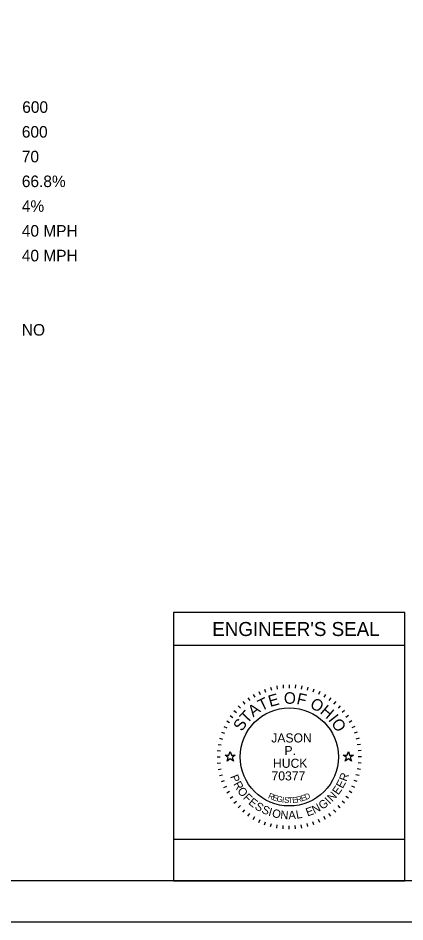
# Model space of a CAD drawing. Extents: x 0 to 34, y 0 to 22.
# Drawn here: x 7.69 to 12.37, y 0 to 10.95 of the extents above; entities that cross this region are included whole.
import ezdxf

# ---------------------------------------------------------------- set-up
doc = ezdxf.new("R2010")
doc.units = 0
for name, color, linetype in [('Default', 7, 'Continuous'), ('SH_Border', 7, 'Continuous'), ('SH_Cut_Line', 7, 'Continuous'), ('SH_Data', 7, 'Continuous'), ('SH_Text', 7, 'Continuous')]:
    doc.layers.add(name, color=color, linetype=linetype)

msp = doc.modelspace()

# ---------------------------------------------------------------- linework, layer by layer
at = {"layer": 'Default'}
for points in [[(10.198, 2.02), (10.245, 2.02), (10.26, 2.065), (10.274, 2.02), (10.321, 2.02), (10.283, 1.992), (10.298, 1.948), (10.26, 1.975), (10.222, 1.948), (10.236, 1.992)], [(11.628, 2.02), (11.675, 2.02), (11.69, 2.065), (11.704, 2.02), (11.751, 2.02), (11.713, 1.992), (11.728, 1.948), (11.69, 1.975), (11.652, 1.948), (11.666, 1.992)]]:
    msp.add_lwpolyline(points, close=True, dxfattribs=at)
at = {"layer": 'SH_Border'}
msp.add_lwpolyline([(1.5, 21.5), (33.5, 21.5), (33.5, 0.5), (1.5, 0.5)], close=True, dxfattribs=at)
at = {"layer": 'SH_Cut_Line'}
msp.add_lwpolyline([(0, 0), (34, 0), (34, 22), (0, 22)], close=True, dxfattribs=at)
at = {"layer": 'SH_Data'}
for p, q in [((12.375, 3.75), (9.575, 3.75)), ((9.575, 3.75), (9.575, 0.5)), ((12.375, 0.5), (12.375, 3.75)), ((12.375, 3.35), (9.575, 3.35)), ((10.823, 2.862), (10.83, 2.822)), ((10.899, 2.872), (10.902, 2.832)), ((10.975, 2.875), (10.975, 2.835)), ((11.051, 2.872), (11.048, 2.832)), ((11.127, 2.862), (11.12, 2.822)), ((10.537, 2.758), (10.557, 2.723)), ((10.605, 2.793), (10.622, 2.757)), ((10.676, 2.822), (10.689, 2.785)), ((10.748, 2.845), (10.759, 2.807)), ((11.201, 2.845), (11.191, 2.807)), ((11.274, 2.822), (11.26, 2.785)), ((11.345, 2.793), (11.328, 2.757)), ((11.412, 2.758), (11.392, 2.723)), ((10.412, 2.67), (10.438, 2.64)), ((10.473, 2.717), (10.496, 2.684)), ((11.477, 2.717), (11.454, 2.684)), ((11.537, 2.67), (11.512, 2.64)), ((10.304, 2.562), (10.335, 2.537)), ((10.356, 2.619), (10.384, 2.59)), ((11.593, 2.619), (11.565, 2.59)), ((11.645, 2.562), (11.614, 2.537)), ((10.217, 2.438), (10.252, 2.418)), ((10.258, 2.502), (10.291, 2.479)), ((11.692, 2.502), (11.659, 2.479)), ((11.733, 2.438), (11.698, 2.418)), ((10.182, 2.37), (10.218, 2.353)), ((11.768, 2.37), (11.732, 2.353)), ((10.13, 2.226), (10.168, 2.216)), ((10.153, 2.299), (10.19, 2.286)), ((11.797, 2.299), (11.759, 2.286)), ((11.82, 2.226), (11.781, 2.216)), ((10.113, 2.152), (10.152, 2.145)), ((11.836, 2.152), (11.797, 2.145)), ((10.1, 2), (10.14, 2)), ((10.103, 2.076), (10.143, 2.073)), ((11.846, 2.076), (11.807, 2.073)), ((11.85, 2), (11.81, 2)), ((10.103, 1.924), (10.143, 1.927)), ((11.846, 1.924), (11.807, 1.927)), ((10.113, 1.848), (10.152, 1.855)), ((10.13, 1.774), (10.168, 1.784)), ((11.82, 1.774), (11.781, 1.784)), ((11.836, 1.848), (11.797, 1.855)), ((10.153, 1.701), (10.19, 1.714)), ((10.182, 1.63), (10.218, 1.647)), ((11.768, 1.63), (11.732, 1.647)), ((11.797, 1.701), (11.759, 1.714)), ((10.217, 1.563), (10.252, 1.583)), ((11.733, 1.563), (11.698, 1.583)), ((10.258, 1.498), (10.291, 1.521)), ((10.304, 1.438), (10.335, 1.463)), ((11.645, 1.438), (11.614, 1.463)), ((11.692, 1.498), (11.659, 1.521)), ((10.356, 1.381), (10.384, 1.41)), ((10.412, 1.33), (10.438, 1.36)), ((10.473, 1.283), (10.496, 1.316)), ((11.477, 1.283), (11.454, 1.316)), ((11.537, 1.33), (11.512, 1.36)), ((11.593, 1.381), (11.565, 1.41)), ((10.537, 1.242), (10.557, 1.277)), ((10.605, 1.207), (10.622, 1.243)), ((10.676, 1.178), (10.689, 1.215)), ((11.274, 1.178), (11.26, 1.215)), ((11.345, 1.207), (11.328, 1.243)), ((11.412, 1.242), (11.392, 1.277)), ((10.748, 1.155), (10.759, 1.193)), ((10.823, 1.138), (10.83, 1.178)), ((10.899, 1.128), (10.902, 1.168)), ((10.975, 1.125), (10.975, 1.165)), ((11.051, 1.128), (11.048, 1.168)), ((11.127, 1.138), (11.12, 1.178)), ((11.201, 1.155), (11.191, 1.193)), ((12.375, 0.5), (9.575, 0.5))]:
    msp.add_line(p, q, dxfattribs=at)
msp.add_lwpolyline([(12.375, 0.5), (12.375, 1), (9.575, 1), (9.575, 0.5)], close=True, dxfattribs=at)
msp.add_circle((10.975, 2), 0.595, dxfattribs=at)

# ---------------------------------------------------------------- texts
for s, height, p in [("ENGINEER'S SEAL", 0.17, (10.042, 3.465)), ('JASON', 0.11, (10.757, 2.175)), ('P.', 0.11, (10.917, 2.022)), ('HUCK', 0.11, (10.778, 1.868)), ('70377', 0.11, (10.76, 1.715))]:
    msp.add_text(s, height=height, dxfattribs=at).set_placement(p)
for s, height, rotation, p in [('E', 0.14, 15.7571, (10.743, 2.604)), ('O', 0.14, 359.7812, (10.909, 2.644)), ('F', 0.14, 347.4362, (11.056, 2.642)), ('A', 0.14, 36.4747, (10.538, 2.478)), ('T', 0.14, 25.7167, (10.636, 2.552)), ('O', 0.14, 332.2586, (11.215, 2.602)), ('H', 0.14, 319.9136, (11.338, 2.536)), ('T', 0.14, 46.4344, (10.463, 2.396)), ('I', 0.14, 308.367, (11.441, 2.448)), ('S', 0.14, 57.1924, (10.403, 2.301)), ('O', 0.14, 303.1491, (11.477, 2.409)), ('P', 0.1, 291.494, (10.257, 1.762)), ('R', 0.1, 69.2322, (11.667, 1.695)), ('R', 0.1, 298.7311, (10.294, 1.672)), ('E', 0.1, 54.758, (11.568, 1.531)), ('E', 0.1, 61.9951, (11.622, 1.61)), ('O', 0.1, 306.4666, (10.34, 1.588)), ('F', 0.1, 314.7068, (10.409, 1.498)), ('R', 0.07, 334.487, (10.712, 1.505)), ('E', 0.07, 341.04, (10.765, 1.48)), ('E', 0.07, 17.6836, (11.125, 1.46)), ('D', 0.07, 23.3052, (11.176, 1.477)), ('N', 0.1, 47.0224, (11.495, 1.451)), ('E', 0.1, 321.4393, (10.473, 1.435)), ('S', 0.1, 328.6764, (10.549, 1.375)), ('G', 0.07, 347.4752, (10.816, 1.462)), ('I', 0.07, 353.7858, (10.884, 1.447)), ('S', 0.07, 356.8926, (10.911, 1.443)), ('T', 0.07, 3.0061, (10.96, 1.439)), ('E', 0.07, 6.0117, (11.014, 1.441)), ('R', 0.07, 11.9184, (11.067, 1.447)), ('N', 0.1, 27.3113, (11.279, 1.308)), ('G', 0.1, 35.0469, (11.373, 1.357)), ('I', 0.1, 43.287, (11.462, 1.421)), ('S', 0.1, 335.9134, (10.631, 1.327)), ('I', 0.1, 343.1505, (10.715, 1.29)), ('O', 0.1, 346.8859, (10.759, 1.275)), ('N', 0.1, 355.1261, (10.864, 1.252)), ('A', 0.1, 2.8617, (10.967, 1.244)), ('L', 0.1, 10.0987, (11.064, 1.249)), ('E', 0.1, 20.0742, (11.196, 1.277))]:
    msp.add_text(s, height=height, rotation=rotation, dxfattribs=at).set_placement(p)
at = {"layer": 'SH_Text'}
for s, p in [('600', (7.742, 9.806)), ('600', (7.737, 9.506)), ('70', (7.737, 9.206)), ('66.8%', (7.737, 8.906)), ('4%', (7.737, 8.606)), ('40 MPH', (7.737, 8.306)), ('40 MPH', (7.737, 8.006)), ('NO', (7.737, 7.106))]:
    msp.add_text(s, height=0.14, dxfattribs=at).set_placement(p)

doc.saveas('drawing.dxf')
